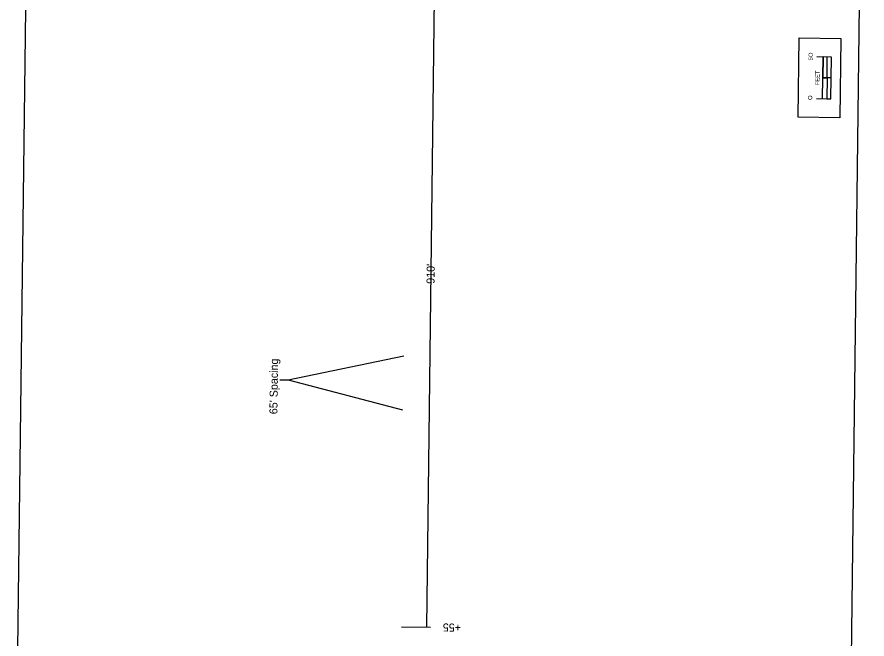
# Model space of a CAD drawing. Extents: x 4959127 to 4960275, y 3872379 to 3884458.
# Drawn here: x 4959256 to 4960275, y 3882967 to 3883713 of the extents above; entities that cross this region are included whole.
import ezdxf

# ---------------------------------------------------------------- set-up
doc = ezdxf.new("R2010")
doc.units = 0
for name, color, linetype in [('dsnCellElements', 7, 'Continuous'), ('dsnCellsScaleBlock', 7, 'Continuous'), ('NamedBoundary', 7, 'Continuous'), ('SheetText', 7, 'Continuous')]:
    doc.layers.add(name, color=color, linetype=linetype)

msp = doc.modelspace()

# ---------------------------------------------------------------- linework, layer by layer
at = {"layer": 'dsnCellElements'}
msp.add_lwpolyline([(4960192.3, 3883592.4), (4960193.4, 3883687.4), (4960243.4, 3883686.8), (4960242.3, 3883591.8)], close=True, dxfattribs=at)
msp.add_lwpolyline([(4960192.3, 3883592.4), (4960193.4, 3883687.4), (4960243.4, 3883686.8), (4960242.3, 3883591.8)], close=True, dxfattribs=at)
at = {"layer": 'dsnCellsScaleBlock'}
msp.add_line((4960231.8, 3883639.5), (4960221.8, 3883639.6), dxfattribs=at)
msp.add_line((4960231.8, 3883639.5), (4960221.8, 3883639.6), dxfattribs=at)
for points in [[(4960242.3, 3883591.8), (4960192.3, 3883592.4), (4960193.4, 3883687.4), (4960243.4, 3883686.8)], [(4960226.8, 3883639.5), (4960227.1, 3883664.5), (4960222.1, 3883664.6), (4960221.8, 3883639.6)], [(4960231.5, 3883614.5), (4960231.8, 3883639.5), (4960226.8, 3883639.5), (4960226.5, 3883614.5)]]:
    msp.add_lwpolyline(points, close=True, dxfattribs=at)
for points in [[(4960214, 3883614.7), (4960231.5, 3883614.5), (4960232.1, 3883664.5), (4960214.7, 3883664.7)], [(4960221.5, 3883614.6), (4960222.1, 3883664.6)]]:
    msp.add_lwpolyline(points, dxfattribs=at)
at = {"layer": 'NamedBoundary'}
msp.add_lwpolyline([(4959255.6, 3882890.7), (4960255.5, 3882878.4), (4960274.7, 3884445.8), (4959274.8, 3884458)], close=True, dxfattribs=at)
at = {"layer": 'SheetText'}
for p, q in [((4959747, 3882981.3), (4959758.1, 3883891.1)), ((4959580.8, 3883277.7), (4959719.6, 3883306.6)), ((4959716.5, 3882981.6), (4959751.5, 3882981.2))]:
    msp.add_line(p, q, dxfattribs=at)
msp.add_lwpolyline([(4959570.7, 3883277.8), (4959580.8, 3883277.7), (4959717.9, 3883241.6)], dxfattribs=at)

# ---------------------------------------------------------------- texts
at = {"layer": 'dsnCellsScaleBlock'}
for s, p in [('5O', (4960209.6, 3883660.7)), ('FEET', (4960217.7, 3883630.7)), ('O', (4960209, 3883613.1))]:
    msp.add_text(s, height=5, rotation=89.2975, dxfattribs=at).set_placement(p)
at = {"layer": 'SheetText'}
for s, rotation, p in [("910'", 89.2908, (4959756.2, 3883392.7)), ("65' Spacing", 89.2908, (4959567.8, 3883236.4)), ('+55', 179.2975, (4959788, 3882985.4))]:
    msp.add_text(s, height=9.6, rotation=rotation, dxfattribs=at).set_placement(p)

doc.saveas('drawing.dxf')
